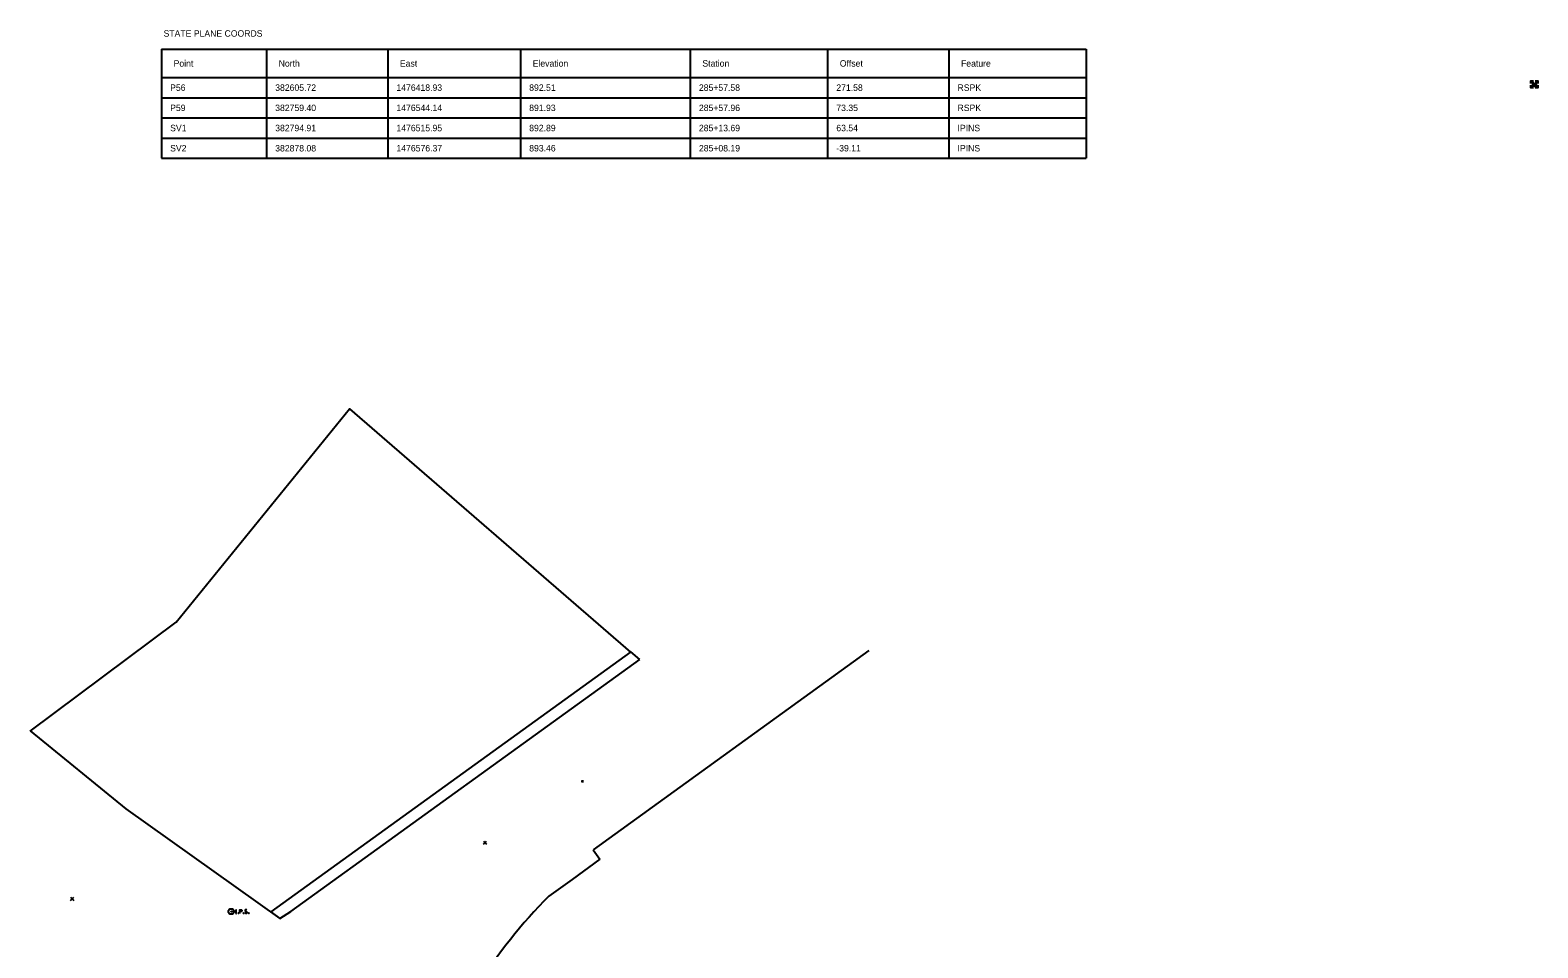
# Model space of a CAD drawing. Extents: x 1474121 to 1496246, y 364907 to 390007.
# Drawn here: x 1476489 to 1477142, y 382862 to 383260 of the extents above; entities that cross this region are included whole.
import ezdxf

# ---------------------------------------------------------------- set-up
doc = ezdxf.new("R2010")
doc.units = 0
for name, color, linetype in [('DV_X_Property_Line', 7, 'Continuous'), ('RW_X_Fee_RW', 7, 'Continuous'), ('SV_P_Mon_Cells_Set', 7, 'Continuous'), ('SV_X_Mon_Cells_Found', 7, 'Continuous'), ('SV_X_Random_Point', 7, 'Continuous'), ('SV_X_Shot_Marker', 7, 'Continuous'), ('SV_X_Text', 7, 'Continuous'), ('SV_X_Text_Elevation', 7, 'Continuous'), ('SV_X_Text_Name', 7, 'Continuous'), ('VG_X_Cells', 7, 'Continuous')]:
    doc.layers.add(name, color=color, linetype=linetype)

msp = doc.modelspace()

# ---------------------------------------------------------------- linework, layer by layer
at = {"layer": 'DV_X_Property_Line'}
msp.add_lwpolyline([(1476489.36, 382956.28), (1476552.48, 383003.4), (1476627.56, 383095.93), (1476749.26, 382990.49)], dxfattribs=at)
at = {"layer": 'RW_X_Fee_RW'}
for p, q in [((1476749.44, 382990.62), (1476593.51, 382877.9)), ((1476602.18, 382878.08), (1476753.33, 382987.24)), ((1476602.18, 382878.08), (1476753.33, 382987.24)), ((1476852.58, 382991.14), (1476733.09, 382904.76)), ((1476753.33, 382987.24), (1476749.44, 382990.62)), ((1476489.27, 382956.35), (1476530.81, 382922.63)), ((1476530.81, 382922.63), (1476597.4, 382875.13)), ((1476733.09, 382904.76), (1476736.05, 382900.73)), ((1476736.05, 382900.73), (1476724.01, 382892.03)), ((1476724.01, 382892.03), (1476713.99, 382884.8)), ((1476593.51, 382877.9), (1476597.4, 382875.13)), ((1476597.4, 382875.13), (1476602.18, 382878.08)), ((1476597.4, 382875.13), (1476602.18, 382878.08))]:
    msp.add_line(p, q, dxfattribs=at)
msp.add_arc((1476865.27, 382733.44), 214, 134.98461, 148.44264, dxfattribs=at)
at = {"layer": 'SV_P_Mon_Cells_Set'}
for points in [[(1476576.47, 382878.12), (1476576.49, 382878.12)], [(1476576.47, 382878.04), (1476576.49, 382878.04)], [(1476576.48, 382878.04), (1476576.48, 382878.12)], [(1476576.53, 382878.05), (1476576.53, 382878.05), (1476576.53, 382878.05), (1476576.53, 382878.04), (1476576.53, 382878.04), (1476576.53, 382878.04), (1476576.53, 382878.04), (1476576.53, 382878.04), (1476576.52, 382878.04), (1476576.52, 382878.04), (1476576.52, 382878.04), (1476576.52, 382878.05), (1476576.53, 382878.05)], [(1476576.56, 382878.04), (1476576.56, 382878.12), (1476576.58, 382878.12), (1476576.59, 382878.12), (1476576.59, 382878.12), (1476576.59, 382878.11), (1476576.59, 382878.11), (1476576.59, 382878.11), (1476576.6, 382878.11), (1476576.6, 382878.1), (1476576.6, 382878.09), (1476576.6, 382878.09), (1476576.6, 382878.09), (1476576.59, 382878.08), (1476576.59, 382878.08), (1476576.59, 382878.08), (1476576.59, 382878.08), (1476576.58, 382878.08), (1476576.56, 382878.08)], [(1476576.64, 382878.05), (1476576.64, 382878.05), (1476576.64, 382878.05), (1476576.64, 382878.04), (1476576.64, 382878.04), (1476576.64, 382878.04), (1476576.64, 382878.04), (1476576.64, 382878.04), (1476576.64, 382878.04), (1476576.63, 382878.04), (1476576.63, 382878.04), (1476576.64, 382878.05), (1476576.64, 382878.05)], [(1476576.71, 382878.11), (1476576.71, 382878.11), (1476576.7, 382878.11), (1476576.7, 382878.12), (1476576.69, 382878.12), (1476576.69, 382878.12), (1476576.69, 382878.12), (1476576.68, 382878.12), (1476576.67, 382878.11), (1476576.67, 382878.11), (1476576.67, 382878.1), (1476576.67, 382878.1), (1476576.67, 382878.09), (1476576.67, 382878.09), (1476576.7, 382878.07), (1476576.71, 382878.07), (1476576.71, 382878.07), (1476576.71, 382878.06), (1476576.71, 382878.06), (1476576.71, 382878.05), (1476576.71, 382878.05), (1476576.71, 382878.05), (1476576.71, 382878.05), (1476576.7, 382878.04), (1476576.7, 382878.04), (1476576.7, 382878.04), (1476576.7, 382878.04), (1476576.7, 382878.04), (1476576.69, 382878.04), (1476576.68, 382878.04), (1476576.68, 382878.04), (1476576.67, 382878.04), (1476576.67, 382878.05)], [(1476576.75, 382878.05), (1476576.75, 382878.05), (1476576.75, 382878.05), (1476576.75, 382878.04), (1476576.75, 382878.04), (1476576.75, 382878.04), (1476576.75, 382878.04), (1476576.75, 382878.04), (1476576.75, 382878.04), (1476576.74, 382878.04), (1476576.74, 382878.04), (1476576.75, 382878.05), (1476576.75, 382878.05)], [(1476578.39, 382878.88), (1476578.74, 382878.88)], [(1476578.39, 382877.28), (1476578.74, 382877.28)], [(1476578.57, 382877.28), (1476578.57, 382878.88)], [(1476579.52, 382877.5), (1476579.58, 382877.5), (1476579.61, 382877.47), (1476579.65, 382877.42), (1476579.65, 382877.36), (1476579.61, 382877.31), (1476579.58, 382877.28), (1476579.52, 382877.28), (1476579.49, 382877.31), (1476579.46, 382877.36), (1476579.46, 382877.42), (1476579.49, 382877.47), (1476579.52, 382877.5)], [(1476580.13, 382877.28), (1476580.13, 382878.88), (1476580.66, 382878.88), (1476580.71, 382878.87), (1476580.79, 382878.84), (1476580.83, 382878.82), (1476580.86, 382878.79), (1476580.9, 382878.73), (1476580.94, 382878.67), (1476580.96, 382878.57), (1476580.96, 382878.42), (1476580.95, 382878.37), (1476580.92, 382878.29), (1476580.88, 382878.2), (1476580.84, 382878.16), (1476580.8, 382878.14), (1476580.75, 382878.11), (1476580.66, 382878.1), (1476580.13, 382878.1)], [(1476581.77, 382877.5), (1476581.83, 382877.5), (1476581.86, 382877.47), (1476581.89, 382877.42), (1476581.89, 382877.36), (1476581.86, 382877.31), (1476581.83, 382877.28), (1476581.77, 382877.28), (1476581.74, 382877.31), (1476581.71, 382877.36), (1476581.71, 382877.42), (1476581.74, 382877.47), (1476581.77, 382877.5)], [(1476583.14, 382878.77), (1476583.12, 382878.79), (1476583.08, 382878.82), (1476582.99, 382878.86), (1476582.86, 382878.88), (1476582.78, 382878.88), (1476582.74, 382878.88), (1476582.6, 382878.84), (1476582.48, 382878.77), (1476582.4, 382878.67), (1476582.38, 382878.57), (1476582.38, 382878.49), (1476582.4, 382878.39), (1476582.49, 382878.3), (1476583.1, 382877.92), (1476583.15, 382877.87), (1476583.17, 382877.82), (1476583.19, 382877.75), (1476583.19, 382877.67), (1476583.18, 382877.6), (1476583.17, 382877.55), (1476583.15, 382877.48), (1476583.13, 382877.43), (1476583.11, 382877.4), (1476583.07, 382877.36), (1476583.04, 382877.33), (1476583, 382877.31), (1476582.96, 382877.29), (1476582.86, 382877.28), (1476582.71, 382877.28), (1476582.61, 382877.31), (1476582.47, 382877.4), (1476582.38, 382877.47)], [(1476583.96, 382877.5), (1476584.01, 382877.5), (1476584.04, 382877.47), (1476584.08, 382877.42), (1476584.08, 382877.36), (1476584.04, 382877.31), (1476584.01, 382877.28), (1476583.96, 382877.28), (1476583.92, 382877.31), (1476583.89, 382877.36), (1476583.89, 382877.42), (1476583.92, 382877.47), (1476583.96, 382877.5)]]:
    msp.add_lwpolyline(points, dxfattribs=at)
for radius in [1.2, 0.06]:
    msp.add_circle((1476576.37, 382878.08), radius, dxfattribs=at)
at = {"layer": 'SV_X_Mon_Cells_Found'}
msp.add_line((1477140.75, 383236.47), (1477140.75, 383236.47), dxfattribs=at)
msp.add_line((1477140.75, 383236.47), (1477140.75, 383236.47), dxfattribs=at)
msp.add_line((1477140.75, 383236.47), (1477140.75, 383236.47), dxfattribs=at)
for points in [[(1477139.25, 383236.85), (1477139.25, 383237.97), (1477140.37, 383237.97)], [(1477140.37, 383234.97), (1477139.25, 383234.97), (1477139.25, 383236.09)], [(1477140.01, 383235.47), (1477140.01, 383237.47), (1477140.75, 383235.47), (1477141.49, 383237.47), (1477141.49, 383235.47)], [(1477140.68, 383236.49), (1477140.68, 383236.55), (1477140.73, 383236.55)], [(1477140.68, 383236.49), (1477140.68, 383236.55), (1477140.73, 383236.55)], [(1477140.73, 383236.4), (1477140.68, 383236.4), (1477140.68, 383236.45)], [(1477140.73, 383236.39), (1477140.68, 383236.39), (1477140.68, 383236.45)], [(1477140.71, 383236.42), (1477140.71, 383236.52), (1477140.75, 383236.42), (1477140.79, 383236.52), (1477140.79, 383236.42)], [(1477140.71, 383236.42), (1477140.71, 383236.52), (1477140.75, 383236.42), (1477140.79, 383236.52), (1477140.79, 383236.42)], [(1477140.77, 383236.55), (1477140.83, 383236.55), (1477140.83, 383236.49)], [(1477140.77, 383236.55), (1477140.83, 383236.55), (1477140.83, 383236.49)], [(1477140.83, 383236.45), (1477140.83, 383236.4), (1477140.77, 383236.4)], [(1477140.83, 383236.45), (1477140.83, 383236.39), (1477140.77, 383236.39)], [(1477141.1, 383237.97), (1477142.25, 383237.97), (1477142.25, 383236.85)], [(1477142.25, 383236.09), (1477142.25, 383234.97), (1477141.1, 383234.97)]]:
    msp.add_lwpolyline(points, dxfattribs=at)
at = {"layer": 'SV_X_Random_Point'}
for p, q in [((1476685.58, 382907.25), (1476686.92, 382908.59)), ((1476685.58, 382908.59), (1476686.92, 382907.25)), ((1476686.22, 382907.89), (1476686.28, 382907.95)), ((1476686.22, 382907.95), (1476686.28, 382907.89)), ((1476506.83, 382882.93), (1476508.17, 382884.27)), ((1476506.83, 382884.27), (1476508.17, 382882.93)), ((1476507.47, 382883.57), (1476507.53, 382883.63)), ((1476507.47, 382883.63), (1476507.53, 382883.57))]:
    msp.add_line(p, q, dxfattribs=at)
at = {"layer": 'SV_X_Shot_Marker'}
for p, q in [((1476728.01, 382934.52), (1476729.01, 382934.52)), ((1476728.48, 382934.52), (1476728.53, 382934.52)), ((1476728.51, 382935.02), (1476728.51, 382934.02)), ((1476728.51, 382934.54), (1476728.51, 382934.49)), ((1476728.51, 382934.52), (1476728.51, 382934.52)), ((1476728.51, 382934.52), (1476728.51, 382934.52))]:
    msp.add_line(p, q, dxfattribs=at)
at = {"layer": 'VG_X_Cells'}
for p, q in [((1476546.19, 383251.67), (1476946.69, 383251.67)), ((1476546.19, 383251.67), (1476546.19, 383204.42)), ((1476591.69, 383251.67), (1476591.69, 383204.42)), ((1476644.19, 383251.67), (1476644.19, 383204.42)), ((1476701.69, 383251.67), (1476701.69, 383204.42)), ((1476775.19, 383251.67), (1476775.19, 383204.42)), ((1476834.69, 383251.67), (1476834.69, 383204.42)), ((1476887.19, 383251.67), (1476887.19, 383204.42)), ((1476946.69, 383251.67), (1476946.69, 383204.42)), ((1476946.69, 383251.67), (1476946.69, 383204.42)), ((1476546.19, 383239.42), (1476946.69, 383239.42)), ((1476546.19, 383230.67), (1476946.69, 383230.67)), ((1476546.19, 383230.67), (1476946.69, 383230.67)), ((1476546.19, 383230.67), (1476946.69, 383230.67)), ((1476546.19, 383230.67), (1476946.69, 383230.67)), ((1476546.19, 383230.67), (1476946.69, 383230.67)), ((1476546.19, 383230.67), (1476946.69, 383230.67)), ((1476546.19, 383230.67), (1476946.69, 383230.67)), ((1476546.19, 383221.92), (1476946.69, 383221.92)), ((1476546.19, 383221.92), (1476946.69, 383221.92)), ((1476546.19, 383221.92), (1476946.69, 383221.92)), ((1476546.19, 383221.92), (1476946.69, 383221.92)), ((1476546.19, 383221.92), (1476946.69, 383221.92)), ((1476546.19, 383221.92), (1476946.69, 383221.92)), ((1476546.19, 383221.92), (1476946.69, 383221.92)), ((1476546.19, 383213.17), (1476946.69, 383213.17)), ((1476546.19, 383213.17), (1476946.69, 383213.17)), ((1476546.19, 383213.17), (1476946.69, 383213.17)), ((1476546.19, 383213.17), (1476946.69, 383213.17)), ((1476546.19, 383213.17), (1476946.69, 383213.17)), ((1476546.19, 383213.17), (1476946.69, 383213.17)), ((1476546.19, 383213.17), (1476946.69, 383213.17)), ((1476546.19, 383204.42), (1476946.69, 383204.42)), ((1476546.19, 383204.42), (1476946.69, 383204.42)), ((1476546.19, 383204.42), (1476946.69, 383204.42)), ((1476546.19, 383204.42), (1476946.69, 383204.42)), ((1476546.19, 383204.42), (1476946.69, 383204.42)), ((1476546.19, 383204.42), (1476946.69, 383204.42)), ((1476546.19, 383204.42), (1476946.69, 383204.42))]:
    msp.add_line(p, q, dxfattribs=at)

# ---------------------------------------------------------------- texts
at = {"layer": 'SV_X_Text'}
msp.add_text('STATE PLANE COORDS', height=2.8, dxfattribs=at).set_placement((1476547.08, 383257.12))
at = {"layer": 'SV_X_Text_Elevation'}
for s, p in [('840.00', (1477140.45, 383236.41)), ('840.00', (1476728.21, 382934.46)), ('840.00', (1476685.95, 382907.86)), ('840.00', (1476507.2, 382883.54)), ('893.46', (1476576.08, 382878.02))]:
    msp.add_text(s, height=0.06, dxfattribs=at).set_placement(p)
at = {"layer": 'SV_X_Text_Name'}
for s, p in [('55', (1477140.67, 383236.47)), ('47', (1476728.42, 382934.52)), ('CLRWA1', (1476685.96, 382907.92)), ('BA11', (1476507.35, 382883.6)), ('SV2', (1476576.23, 382878.08))]:
    msp.add_text(s, height=0.06, dxfattribs=at).set_placement(p)
at = {"layer": 'VG_X_Cells'}
for s, p in [('Point', (1476551.44, 383244.15)), ('North', (1476596.94, 383244.15)), ('East', (1476649.44, 383244.15)), ('Elevation', (1476706.94, 383244.15)), ('Station', (1476780.44, 383244.15)), ('Offset', (1476839.94, 383244.15)), ('Feature', (1476892.44, 383244.15)), ('P56', (1476549.94, 383233.65)), ('382605.72', (1476595.44, 383233.65)), ('1476418.93', (1476647.94, 383233.65)), ('892.51', (1476705.44, 383233.65)), ('285+57.58', (1476778.94, 383233.65)), ('271.58', (1476838.44, 383233.65)), ('RSPK', (1476890.94, 383233.65)), ('P59', (1476549.94, 383224.9)), ('382759.40', (1476595.44, 383224.9)), ('1476544.14', (1476647.94, 383224.9)), ('891.93', (1476705.44, 383224.9)), ('285+57.96', (1476778.94, 383224.9)), ('73.35', (1476838.44, 383224.9)), ('RSPK', (1476890.94, 383224.9)), ('SV1', (1476549.94, 383216.15)), ('382794.91', (1476595.44, 383216.15)), ('1476515.95', (1476647.94, 383216.15)), ('892.89', (1476705.44, 383216.15)), ('285+13.69', (1476778.94, 383216.15)), ('63.54', (1476838.44, 383216.15)), ('IPINS', (1476890.94, 383216.15)), ('SV2', (1476549.94, 383207.4)), ('382878.08', (1476595.44, 383207.4)), ('1476576.37', (1476647.94, 383207.4)), ('893.46', (1476705.44, 383207.4)), ('285+08.19', (1476778.94, 383207.4)), ('-39.11', (1476838.44, 383207.4)), ('IPINS', (1476890.94, 383207.4))]:
    msp.add_text(s, height=2.8, dxfattribs=at).set_placement(p)

doc.saveas('drawing.dxf')
